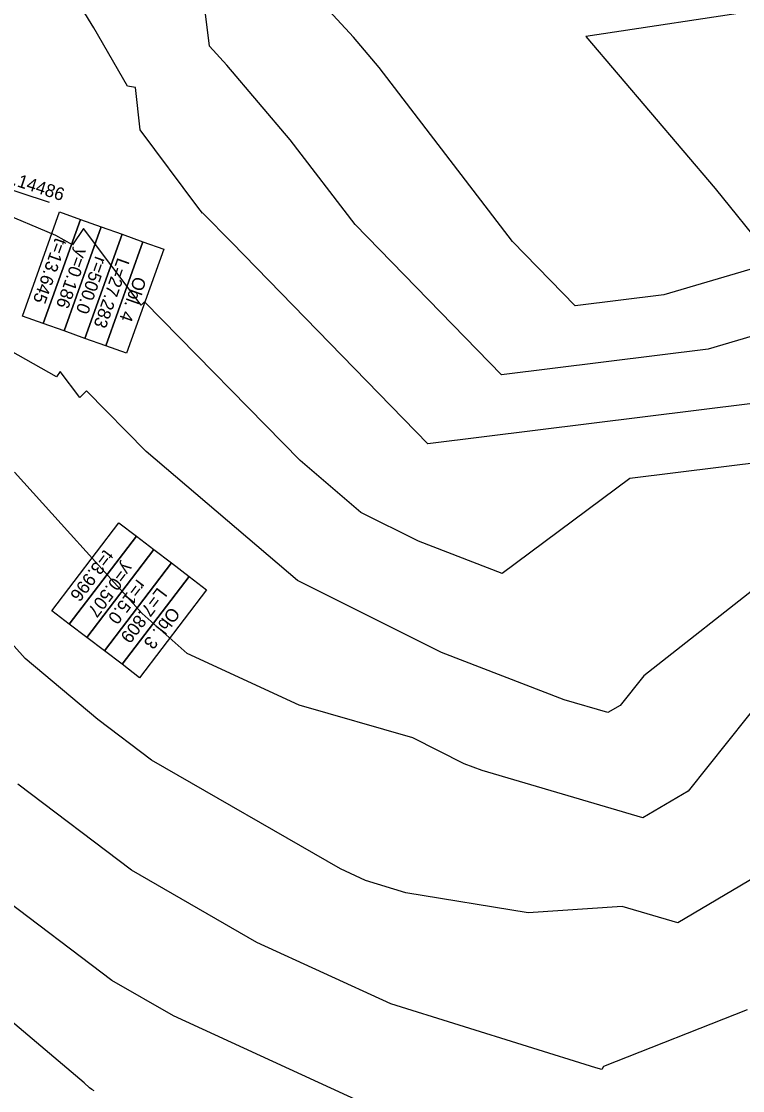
# Model space of a CAD drawing. Extents: x -549394 to -546608, y -1037055 to -1033629.
# Drawn here: x -548663.6 to -548467.8, y -1034491.4 to -1034201.2 of the extents above; entities that cross this region are included whole.
import ezdxf

# ---------------------------------------------------------------- set-up
doc = ezdxf.new("R2010")
doc.units = 0
for name, color, linetype in [('hlavni_vrst', 7, 'Continuous'), ('norm_vrst', 7, 'Continuous'), ('x_popis_oblouky_C122', 7, 'Continuous')]:
    doc.layers.add(name, color=color, linetype=linetype)

msp = doc.modelspace()

# ---------------------------------------------------------------- linework, layer by layer
at = {"layer": 'hlavni_vrst'}
for p, q in [((-548654.02, -1034297.71), (-548668.6, -1034289.46)), ((-548653.01, -1034296.2), (-548654.02, -1034297.71)), ((-548647.73, -1034303.24), (-548653.01, -1034296.2)), ((-548645.86, -1034301.43), (-548647.73, -1034303.24)), ((-548629.71, -1034317.92), (-548645.86, -1034301.43)), ((-548588.64, -1034352.94), (-548629.71, -1034317.92)), ((-548439.33, -1034335.33), (-548494.69, -1034378.78)), ((-548549.58, -1034372.48), (-548588.64, -1034352.94)), ((-548516.22, -1034385.34), (-548549.58, -1034372.48)), ((-548494.69, -1034378.78), (-548501.11, -1034386.84)), ((-548504.43, -1034388.79), (-548516.22, -1034385.34)), ((-548501.11, -1034386.84), (-548504.43, -1034388.79)), ((-548646.53, -1034489.27), (-548696.43, -1034447.05)), ((-548645.09, -1034490.62), (-548646.53, -1034489.27)), ((-548644.45, -1034491.01), (-548645.09, -1034490.62)), ((-548643.76, -1034491.42), (-548644.45, -1034491.01))]:
    msp.add_line(p, q, dxfattribs=at)
at = {"layer": 'norm_vrst'}
for p, q in [((-548573.46, -1034205.49), (-548594.36, -1034182.69)), ((-548643.93, -1034203.01), (-548647.02, -1034197.79)), ((-548612.48, -1034207.99), (-548613.85, -1034197)), ((-548450.86, -1034196.34), (-548510.41, -1034205.32)), ((-548634.8, -1034218.77), (-548643.93, -1034203.01)), ((-548566.45, -1034213.77), (-548573.46, -1034205.49)), ((-548510.41, -1034205.32), (-548475.29, -1034246.59)), ((-548607.79, -1034213.12), (-548612.48, -1034207.99)), ((-548590.6, -1034233.4), (-548607.79, -1034213.12)), ((-548530.3, -1034260.92), (-548566.45, -1034213.77)), ((-548632.63, -1034219.17), (-548634.8, -1034218.77)), ((-548631.36, -1034230.66), (-548632.63, -1034219.17)), ((-548615.63, -1034251.62), (-548631.36, -1034230.66)), ((-548572.99, -1034256.36), (-548590.6, -1034233.4)), ((-548475.29, -1034246.59), (-548459.16, -1034266.61)), ((-548654.22, -1034259.32), (-548673.3, -1034251.25)), ((-548614.38, -1034253.29), (-548615.63, -1034251.62)), ((-548614.34, -1034253.24), (-548614.38, -1034253.29)), ((-548606.49, -1034261.26), (-548614.34, -1034253.24)), ((-548533.29, -1034297.15), (-548572.99, -1034256.36)), ((-548649.7, -1034261.88), (-548654.22, -1034259.32)), ((-548646.69, -1034257.42), (-548649.7, -1034261.88)), ((-548631.06, -1034278.27), (-548646.69, -1034257.42)), ((-548553.29, -1034315.9), (-548606.49, -1034261.26)), ((-548513.28, -1034278.39), (-548530.3, -1034260.92)), ((-548459.16, -1034266.61), (-548489.25, -1034275.39)), ((-548407, -1034269.64), (-548477.2, -1034290.13)), ((-548489.25, -1034275.39), (-548513.28, -1034278.39)), ((-548630.1, -1034277.34), (-548631.06, -1034278.27)), ((-548587.9, -1034320.42), (-548630.1, -1034277.34)), ((-548477.2, -1034290.13), (-548533.29, -1034297.15)), ((-548465.15, -1034304.87), (-548553.29, -1034315.9)), ((-548571.43, -1034334.47), (-548587.9, -1034320.42)), ((-548453.11, -1034319.62), (-548498.48, -1034325.29)), ((-548630.74, -1034361.88), (-548665.39, -1034323.55)), ((-548498.48, -1034325.29), (-548533.12, -1034351.03)), ((-548555.75, -1034342.31), (-548571.43, -1034334.47)), ((-548662.5, -1034374.07), (-548691.08, -1034342.45)), ((-548533.12, -1034351.03), (-548555.75, -1034342.31)), ((-548618.59, -1034372.71), (-548630.74, -1034361.88)), ((-548588.13, -1034386.75), (-548618.59, -1034372.71)), ((-548642.83, -1034390.68), (-548662.5, -1034374.07)), ((-548458.85, -1034380.25), (-548482.64, -1034410.07)), ((-548557.36, -1034395.67), (-548588.13, -1034386.75)), ((-548628.29, -1034401.66), (-548642.83, -1034390.68)), ((-548543.41, -1034402.65), (-548557.36, -1034395.67)), ((-548576.92, -1034431.22), (-548628.29, -1034401.66)), ((-548538.56, -1034404.52), (-548543.41, -1034402.65)), ((-548494.91, -1034417.3), (-548538.56, -1034404.52)), ((-548633.63, -1034431.57), (-548664.52, -1034408.24)), ((-548482.64, -1034410.07), (-548494.91, -1034417.3)), ((-548638.98, -1034461.47), (-548686.2, -1034425.81)), ((-548599.62, -1034451.14), (-548633.63, -1034431.57)), ((-548570.13, -1034434.34), (-548576.92, -1034431.22)), ((-548464.16, -1034433.3), (-548485.39, -1034445.81)), ((-548559.27, -1034437.72), (-548570.13, -1034434.34)), ((-548525.99, -1034443.12), (-548559.27, -1034437.72)), ((-548500.52, -1034441.38), (-548525.99, -1034443.12)), ((-548485.39, -1034445.81), (-548500.52, -1034441.38)), ((-548563.3, -1034467.8), (-548599.62, -1034451.14)), ((-548622.32, -1034471.06), (-548638.98, -1034461.47)), ((-548507.64, -1034485.13), (-548563.3, -1034467.8)), ((-548556.48, -1034501.26), (-548622.32, -1034471.06)), ((-548466.59, -1034469.42), (-548505.56, -1034484.82)), ((-548506.07, -1034485.64), (-548507.64, -1034485.13)), ((-548505.56, -1034484.82), (-548506.07, -1034485.64))]:
    msp.add_line(p, q, dxfattribs=at)
at = {"layer": 'x_popis_oblouky_C122'}
msp.add_lwpolyline([(-548695.37, -1034237.37), (-548656.05, -1034250.25)], dxfattribs=at)
for points in [[(-548647.52, -1034254.96), (-548657.61, -1034283.21), (-548663.26, -1034281.2), (-548653.18, -1034252.94)], [(-548641.87, -1034256.97), (-548651.95, -1034285.23), (-548657.61, -1034283.21), (-548647.52, -1034254.96)], [(-548636.22, -1034258.99), (-548646.3, -1034287.25), (-548651.95, -1034285.23), (-548641.87, -1034256.97)], [(-548630.57, -1034261.01), (-548640.65, -1034289.26), (-548646.3, -1034287.25), (-548636.22, -1034258.99)], [(-548624.92, -1034263.02), (-548635, -1034291.28), (-548640.65, -1034289.26), (-548630.57, -1034261.01)], [(-548632.36, -1034340.9), (-548650.55, -1034364.76), (-548655.32, -1034361.13), (-548637.14, -1034337.27)], [(-548627.59, -1034344.54), (-548645.78, -1034368.4), (-548650.55, -1034364.76), (-548632.36, -1034340.9)], [(-548622.82, -1034348.18), (-548641.01, -1034372.04), (-548645.78, -1034368.4), (-548627.59, -1034344.54)], [(-548618.05, -1034351.82), (-548636.24, -1034375.68), (-548641.01, -1034372.04), (-548622.82, -1034348.18)], [(-548613.28, -1034355.45), (-548631.46, -1034379.31), (-548636.24, -1034375.68), (-548618.05, -1034351.82)]]:
    msp.add_lwpolyline(points, close=True, dxfattribs=at)

# ---------------------------------------------------------------- texts
for s, rotation, p in [('KT 0.14486', 341.8627, (-548675.55, -1034242.49)), ('t=13.645', 250.3877, (-548654.32, -1034259.74)), ('y=0.186', 250.3877, (-548648.57, -1034262.53)), ('r=500.0', 250.3877, (-548643.46, -1034264.73)), ('L=27.283', 250.3877, (-548637.42, -1034265.15)), ('Obl. 4', 250.3877, (-548632.84, -1034270.19)), ('t=3.996', 232.7059, (-548641, -1034344.32)), ('y=0.507', 232.7059, (-548635.66, -1034347.8)), ('r=15.0', 232.7059, (-548632.16, -1034352.38)), ('L=7.809', 232.7059, (-548626.54, -1034354.61)), ('Obl. 3', 232.7059, (-548623, -1034359.88))]:
    msp.add_text(s, height=3.5, rotation=rotation, dxfattribs=at).set_placement(p)

doc.saveas('drawing.dxf')
